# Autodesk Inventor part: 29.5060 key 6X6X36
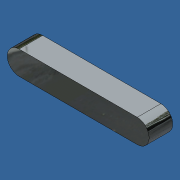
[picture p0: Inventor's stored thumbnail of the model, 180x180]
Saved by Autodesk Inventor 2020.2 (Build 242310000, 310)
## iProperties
Created: 2020-08
Part Number: 29.5060 key 6X6X36
Material: Steel
Document SubType Name: Modeling
Designer: amoles
Density: 7.85 g/cm^3
Appearance: Zinc
Mass: 9.80972 g
Surface Area: 8.89646 cm^2
Volume: 1.24965 cm^3
Author: amoles
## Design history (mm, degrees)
sketch "Sketch1"
  geometry: L1 (-15, -3)-(15, -3); L2 (15, 3)-(-15, 3); A1 r 3 centre (-15, 0) between (-15, -3) and (-15, 3); A2 r 3 centre (15, 0) between (15, -3) and (15, 3); 1 further point
  constraints: 4 end point, 4 point on circle, 2 centre point, 2 horizontal alignment, 2 tangent, 1 parallel
  dimensions: "d0" = 6 diameter of A1; "d1" = 15 distance of point (0, 0) A1.centre; "d2" = 15 distance of A2.centre point (0, 0); "d3" = 6 diameter of A2
extrude "Extrusion1" new body sketch "Sketch1" distance "d4" = 6; taper "d5" = 0 deg
body "Solid1"
